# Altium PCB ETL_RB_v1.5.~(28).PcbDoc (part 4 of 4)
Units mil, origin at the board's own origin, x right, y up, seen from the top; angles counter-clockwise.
Board outline 5129.92 x 2224.41 mil, 8 copper layers (Top Layer, plane 1, M1, plane 2, plane 3, M2, plane 4, Bottom Layer), stack 36.907 mil thick; 212 components, 186 nets, 1961 pads, 978 vias.
Unrouted connection lines stored in the file: 395.
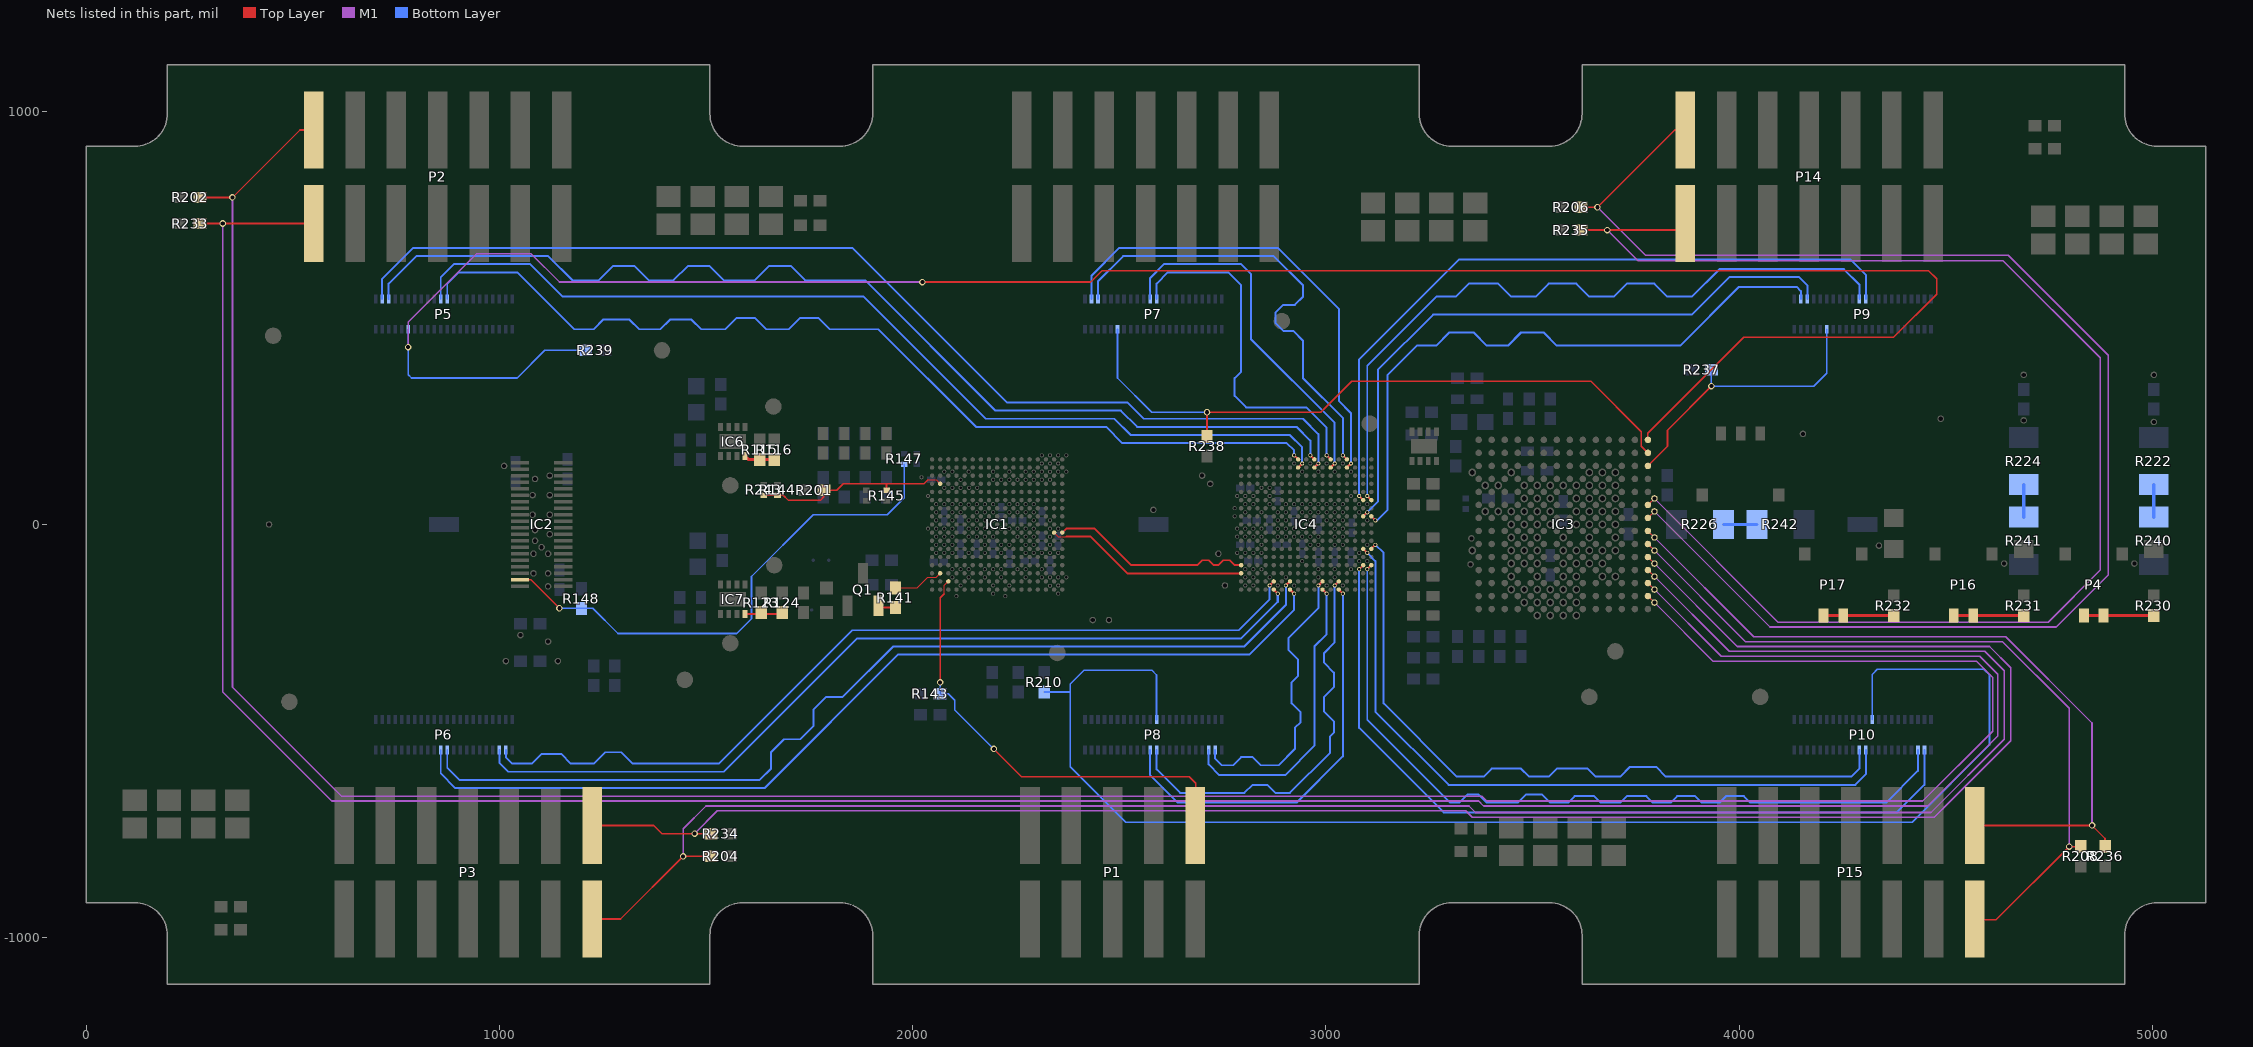
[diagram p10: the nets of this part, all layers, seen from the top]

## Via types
v1: diameter 15.75, hole 9.84, Top Layer to Bottom Layer, 978 vias

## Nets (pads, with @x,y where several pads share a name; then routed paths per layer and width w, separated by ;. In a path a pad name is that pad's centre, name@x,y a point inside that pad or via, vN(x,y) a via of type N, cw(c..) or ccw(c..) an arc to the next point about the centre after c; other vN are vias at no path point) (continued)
NetIC6_4: IC6.4 R115.1 R116.2 | length 74.1
  Top Layer w7.87: IC6.4@1594.49,165.35 1602.36,157.48 R115.1@1629.92,157.48 R116.2@1665.35,157.48
NetIC7_4: IC7.4 R123.1 R124.2 | length 92.2
  Top Layer w4.02: IC7.4@1594.49,-216.54 1681.1,-216.54 R124.2@1685.04,-212.6
NetP4_1: P4.1 P4.2 R230.2 | length 169.3
  Top Layer w8: P4.1@4834.65,-220.47 P4.2@4881.89,-220.47 R230.2@5003.94,-220.47
NetP8_11: P8.11 P10.12 R210.1 | length 3530.4
  Bottom Layer w4: R210.1@2318.9,-405.51 2381.89,-405.51 ; P8.11@2590.55,-472.44 2590.55,-364.17 2578.74,-352.36 2415.35,-352.36 2381.89,-385.83 2381.89,-405.51 ; P10.12@4322.83,-472.44 4322.83,-362.2 4334.65,-350.39 4592.52,-350.39 4606.3,-364.17 4606.3,-533.46 4419.29,-720.47 3011.81,-720.47 2515.75,-720.47 2381.89,-586.61 2381.89,-405.51
NetP16_1: P16.1 P16.2 R231.2 | length 169.3
  Top Layer w8: P16.1@4519.69,-220.47 P16.2@4566.93,-220.47 R231.2@4688.98,-220.47
NetP17_1: P17.1 P17.2 R232.2 | length 169.3
  Top Layer w8: P17.1@4204.72,-220.47 P17.2@4251.97,-220.47 R232.2@4374.02,-220.47
NetQ1_2: Q1.2 R141.2 | length 43
  Top Layer w5: Q1.2@1917.32,-196.85 1921.26,-200.79 R141.2@1958.66,-200.79
NetR222_2: R222.2 R240.1 | length 78.7
  Bottom Layer w8: R240.1@5003.94,17.72 R222.2@5003.94,96.46
NetR224_2: R224.2 R241.1 | length 78.7
  Bottom Layer w8: R241.1@4688.98,17.72 R224.2@4688.98,96.46
NetR226_2: R226.2 R242.1 | length 80.7
  Bottom Layer w8: R226.2@3962.6,0 R242.1@4043.31,0
ON0: IC3.A12 P2.1 pad.1@3795.28,-157.48 R233.1 | length 6976.4
  Top Layer w4: R233.1@275.59,728.35 v1(330.71,728.35) P2.1@551.18,728.35
  Top Layer w4.02: IC3.A12@3779.53,-141.73 pad.1@3795.28,-157.48
  M1 w4: v1(330.71,728.35) 330.71,-405.51 594.49,-669.29 3370.08,-669.29 3381.89,-681.1 4456.69,-681.1 4625.98,-511.81 4625.98,-362.2 4582.68,-318.9 3956.69,-318.9 pad.1@3795.28,-157.48
ON1: IC3.A10 P3.1 pad.1@3795.28,-94.49 R234.1 | length 4752.6
  Top Layer w4.02: P3.1@1224.41,-728.35 1374.02,-728.35 1393.7,-748.03 v1(1472.44,-748.03) R234.1@1511.81,-748.03 ; IC3.A10@3779.53,-78.74 pad.1@3795.28,-94.49
  M1 w4.02: v1(1472.44,-748.03) 1527.56,-692.91 3338.58,-692.91 3354.33,-708.66 4472.44,-708.66 4657.48,-523.62 4657.48,-346.46 4606.3,-295.28 3996.06,-295.28 pad.1@3795.28,-94.49
ON2: IC3.A6 P14.1 pad.1@3795.28,62.99 R235.1 | length 3370.3
  Top Layer w4: R235.1@3618.11,712.6 3854.33,712.6 P14.1@3870.08,728.35 ; IC3.A6@3779.53,47.24 pad.1@3795.28,62.99
  M1 w4: v1(3681.1,712.6) 3755.91,637.8 4639.76,637.8 4874.02,403.54 4874.02,-110.24 4748.03,-236.22 4094.49,-236.22 pad.1@3795.28,62.99
ON3: IC3.A8 P15.1 pad.1@3795.28,-31.5 R236.1 | length 1863
  Top Layer w4: IC3.A8@3779.53,-15.75 pad.1@3795.28,-31.5 ; P15.1@4570.87,-728.35 v1(4854.33,-728.35) 4885.83,-759.84 R236.1@4885.83,-779.53
  M1 w4: pad.1@3795.28,-31.5 4035.43,-271.65 4645.67,-271.65 4854.33,-480.32 v1(4854.33,-728.35)
PG0: IC3.A13 P2.2 pad.1@3795.28,-188.98 R202.1 | length 7018.5
  Top Layer w4.02: R202.1@275.59,791.34 v1(354.33,791.34) 517.72,954.72 P2.2@551.18,954.72 ; IC3.A13@3779.53,-173.23 pad.1@3795.28,-188.98
  M1 w4.02: v1(354.33,791.34) 354.33,-393.7 618.11,-657.48 3377.95,-657.48 3389.76,-669.29 4444.88,-669.29 4614.17,-500 4614.17,-370.08 4574.8,-330.71 3937.01,-330.71 pad.1@3795.28,-188.98
PG1: IC3.A11 P3.2 pad.1@3795.27,-125.98 R204.1 | length 4845.4
  Top Layer w4: P3.2@1224.41,-954.72 1293.31,-954.72 v1(1444.88,-803.15) R204.1@1511.81,-803.15 ; IC3.A11@3779.53,-110.24 pad.1@3795.27,-125.98
  M1 w4: v1(1444.88,-803.15) 1444.88,-736.22 1500,-681.1 3346.46,-681.1 3362.2,-696.85 4464.57,-696.85 4641.73,-519.68 4641.73,-354.33 4594.49,-307.09 3976.38,-307.09 pad.1@3795.27,-125.98
PG2: IC3.A7 P14.2 pad.1@3795.28,31.5 R206.1 | length 3534.2
  Top Layer w4.02: R206.1@3618.11,767.72 v1(3657.48,767.72) 3844.49,954.72 P14.2@3870.08,954.72 ; IC3.A7@3779.53,15.75 pad.1@3795.28,31.5
  M1 w4.02: v1(3657.48,767.72) 3773.62,651.57 4651.57,651.57 4893.7,409.45 4893.7,-122.05 4767.72,-248.03 4074.8,-248.03 pad.1@3795.28,31.5
PG3: IC3.A9 P15.2 pad.1@3795.28,-62.99 R208.1 | length 1849.1
  Top Layer w4.02: IC3.A9@3779.53,-47.24 pad.1@3795.28,-62.99 ; P15.2@4570.87,-954.72 4572.83,-956.69 4622.05,-956.69 v1(4799.21,-779.53) R208.1@4826.77,-779.53
  M1 w4.02: pad.1@3795.28,-62.99 4015.75,-283.46 4637.8,-283.46 4799.21,-444.88 v1(4799.21,-779.53)
READY0: IC1.R2 R141.1 | length 122.9
  Top Layer w3: R141.1@1958.66,-153.54 2011.81,-153.54 2037.4,-127.95 2057.09,-127.95 IC1.R2@2066.93,-118.11
REFCLKN: IC1.K17 IC4.P1 | length 493.4
  Top Layer w4.72: IC1.K17@2362.2,-19.68 2372.05,-9.84 2440.94,-9.84 2529.53,-98.42 2688.98,-98.42 2700.79,-86.61 2716.54,-86.61 2728.35,-98.42 2740.16,-98.42 2751.97,-86.61 2767.72,-86.61 2779.53,-98.42 IC4.P1@2795.28,-98.43
REFCLKP: IC1.K16 IC4.R1 | length 493.5
  Top Layer w3: IC1.K16@2342.52,-19.68 2352.36,-29.53 2372.05,-29.53
  Top Layer w4.72: 2372.05,-29.53 2431.1,-29.53 2519.68,-118.11 IC4.R1@2795.28,-118.11
RSSI: IC2.4 R147.2 R148.1 | length 1261
  Top Layer w4: IC2.4@1050,-133.86 1076.77,-133.86 v1(1145.67,-202.76)
  Bottom Layer w4: v1(1145.67,-202.76) R148.1@1198.82,-202.76 1226.38,-202.76 1287.4,-263.78 1574.8,-263.78 1610.24,-228.35 1610.24,-125.98 1759.84,23.62 1938.98,23.62 1980.31,64.96 R147.2@1980.31,145.67
RSTB0: IC3.A1 P5.16 R239.1 | length 5338.2
  Top Layer w4: v1(2023.62,586.61) 2431.1,586.61 2458.66,614.17 4458.66,614.17 4478.35,594.49 4478.35,557.09 4374.02,452.76 4011.81,452.76 3779.53,220.47 IC3.A1@3779.53,204.72
  M1 w4: v1(779.53,429.13) 779.53,490.16 944.88,655.51 1076.77,655.51 1145.67,586.61 v1(2023.62,586.61)
  Bottom Layer w4: P5.16@779.53,472.44 v1(779.53,429.13) 779.53,362.2 787.4,354.33 1043.31,354.33 1110.24,421.26 R239.1@1208.66,421.26
RSTB1: IC3.A2 P7.16 pad.1@2712.6,271.65 R238.1 | length 1618.4
  Top Layer w4: R238.1@2712.6,212.6 pad.1@2712.6,271.65 2988.19,271.65 3062.99,346.46 3641.73,346.46 3763.78,224.41 3763.78,188.98 IC3.A2@3779.53,173.23
  Bottom Layer w4: P7.16@2496.06,472.44 2496.06,354.33 2578.74,271.65 pad.1@2712.6,271.65
RSTB2: IC3.A3 P9.16 R237.1 | length 694.8
  Top Layer w4: IC3.A3@3779.53,141.73 3826.77,188.98 3826.77,228.35 v1(3933.07,334.65)
  Bottom Layer w4: R237.1@3933.07,374.02 v1(3933.07,334.65) 4181.1,334.65 4212.6,366.14 P9.16@4212.6,472.44
SC_I2C: IC1.T3 P1.1 R143.2 | length 1105.2
  Top Layer w3: 2076.77,-167.32 2076.77,-147.64 IC1.T3@2086.61,-137.79
  Top Layer w4: v1(2066.93,-381.89) 2066.93,-177.16 2076.77,-167.32 ; v1(2196.85,-543.31) 2263.78,-610.24 2383.86,-610.24 ; 2384.25,-610.63 2383.86,-610.24 ; P1.1@2685.04,-728.35 2685.04,-625.98 2669.29,-610.24 2383.86,-610.24
  Top Layer w39.37: P1.1@2684.25,-728.35 P1.1@2685.04,-728.35
  Bottom Layer w4: v1(2066.93,-381.89) R143.2@2066.93,-409.45 2086.61,-409.45 2102.36,-425.2 2102.36,-448.82 v1(2196.85,-543.31)
T_EDIN00N: IC4.U5 P6.22 pad.1@2883.86,-167.32 | length 2128.3
  Top Layer w5.12: IC4.U5@2874.02,-157.48 pad.1@2883.86,-167.32
  Bottom Layer w4.72: P6.22@1000,-545.28 1000,-576.77 1021.65,-598.43 1543.31,-598.43 1866.14,-275.59 2696.85,-275.59
  Bottom Layer w5.12: 2696.85,-275.59 2795.28,-275.59 2883.86,-187.01 pad.1@2883.86,-167.32
T_EDIN00P: IC4.T5 P6.21 pad.1@2864.17,-147.64 | length 2127.2
  Top Layer w5.12: pad.1@2864.17,-147.64 IC4.T5@2874.02,-137.8
  Bottom Layer w4.72: P6.21@1015.75,-545.28 1015.75,-562.99 1031.5,-578.74 1078.74,-578.74 1102.36,-555.12 1149.61,-555.12 1173.23,-578.74 1228.35,-578.74 1255.91,-551.18 1295.28,-551.18 1322.83,-578.74 1531.5,-578.74 1854.33,-255.91 2789.37,-255.91 2864.17,-181.1 pad.1@2864.17,-147.64
T_EDIN02N: IC4.U7 P6.31 pad.1@2923.23,-167.32 | length 2368.6
  Top Layer w5.12: IC4.U7@2913.39,-157.48 pad.1@2923.23,-167.32
  Bottom Layer w4.72: P6.31@858.27,-545.28 858.27,-602.36 893.7,-637.8 1641.73,-637.8 1964.57,-314.96 2814.96,-314.96 2923.23,-206.69 pad.1@2923.23,-167.32
T_EDIN02P: IC4.T7 P6.30 pad.1@2903.54,-147.64 | length 2367.7
  Top Layer w5.12: pad.1@2903.54,-147.64 IC4.T7@2913.39,-137.8
  Bottom Layer w4.72: P6.30@874.02,-545.28 874.02,-588.58 903.54,-618.11 1629.92,-618.11 1657.48,-590.55 1657.48,-551.18 1688.98,-519.68 1728.35,-519.68 1759.84,-488.19 1759.84,-448.82 1791.34,-417.32 1830.71,-417.32 1952.76,-295.28 2803.15,-295.28 2903.54,-194.88 pad.1@2903.54,-147.64
T_EDIN10N: IC4.U11 P8.22 pad.1@3001.97,-167.32 | length 725.6
  Top Layer w5.12: IC4.U11@2992.13,-157.48 pad.1@3001.97,-167.32
  Bottom Layer w4.72: P8.22@2716.54,-545.28 2716.54,-580.71 2742.13,-606.3 2901.57,-606.3 2972.44,-535.43 2972.44,-295.28 3001.97,-265.75 pad.1@3001.97,-167.32
T_EDIN10P: IC4.T11 P8.21 pad.1@2982.28,-147.64 | length 724.4
  Top Layer w5.12: pad.1@2982.28,-147.64 IC4.T11@2992.13,-137.8
  Bottom Layer w4.72: P8.21@2732.28,-545.28 2732.28,-566.93 2748.03,-582.68 2775.59,-582.68 2795.28,-562.99 2822.83,-562.99 2842.52,-582.68 2885.83,-582.68 2925.2,-543.31 2925.2,-492.13 2938.98,-478.35 2938.98,-454.72 2917.32,-433.07 2917.32,-381.89 2933.07,-366.14 2933.07,-326.77 2909.45,-303.15 2909.45,-275.59 2982.28,-202.76 pad.1@2982.28,-147.64
T_EDIN12N: IC4.U13 P8.31 pad.1@3041.34,-167.32 | length 1009.4
  Top Layer w5.12: IC4.U13@3031.5,-157.48 pad.1@3041.34,-167.32
  Bottom Layer w4.72: P8.31@2574.8,-545.28 2574.8,-606.3 2641.73,-673.23 2929.13,-673.23 3041.34,-561.02 pad.1@3041.34,-167.32
T_EDIN12P: IC4.T13 P8.30 pad.1@3021.65,-147.64 | length 1009.9
  Top Layer w5.12: pad.1@3021.65,-147.64 IC4.T13@3031.5,-137.8
  Bottom Layer w4.72: P8.30@2590.55,-545.28 2590.55,-592.52 2647.64,-649.61 2803.15,-649.61 2822.83,-629.92 2858.27,-629.92 2877.95,-649.61 2913.39,-649.61 3009.84,-553.15 3009.84,-513.78 3019.69,-503.94 3019.69,-476.38 2996.06,-452.76 2996.06,-417.32 3019.69,-393.7 3019.69,-358.27 2996.06,-334.65 2996.06,-311.02 3021.65,-285.43 pad.1@3021.65,-147.64
T_EDIN20N: IC4.P17 P10.22 pad.1@3100.39,-108.27 | length 1961.7
  Top Layer w5.12: pad.1@3100.39,-108.27 IC4.P17@3110.24,-98.43
  Bottom Layer w4.72: pad.1@3100.39,-108.27 3100.39,-472.44 3301.18,-673.23 3322.83,-673.23 3342.52,-653.54 3370.08,-653.54 3389.76,-673.23 3464.57,-673.23 3484.25,-653.54 3523.62,-653.54 3543.31,-673.23 3586.61,-673.23 3602.36,-657.48 3649.61,-657.48 3665.35,-673.23 3712.6,-673.23 3728.35,-657.48 3775.59,-657.48 3791.34,-673.23 3834.65,-673.23 3850.39,-657.48 3893.7,-657.48 3909.45,-673.23 3952.76,-673.23 3968.5,-657.48 4011.81,-657.48 4027.56,-673.23 4356.3,-673.23 4433.07,-596.46 P10.22@4433.07,-545.28
T_EDIN20P: IC4.P16 P10.21 pad.1@3080.71,-108.27 | length 1963.1
  Top Layer w5.12: pad.1@3080.71,-108.27 IC4.P16@3090.55,-98.43
  Bottom Layer w4.72: pad.1@3080.71,-108.27 3080.71,-492.13 3285.43,-696.85 4381.89,-696.85 4448.82,-629.92 P10.21@4448.82,-545.28
T_EDIN22N: IC4.M17 P10.31 pad.1@3120.08,-49.21 | length 1736.5
  Top Layer w5.12: IC4.M17@3110.24,-59.05 pad.1@3120.08,-49.21
  Bottom Layer w4.72: pad.1@3120.08,-49.21 3139.76,-68.9 3139.76,-433.07 3316.93,-610.24 3381.89,-610.24 3401.57,-590.55 3472.44,-590.55 3492.13,-610.24 3539.37,-610.24 3559.06,-590.55 3633.86,-590.55 3653.54,-610.24 3712.6,-610.24 3736.22,-586.61 3799.21,-586.61 3822.83,-610.24 4271.65,-610.24 4291.34,-590.55 P10.31@4291.34,-545.28
T_EDIN22P: IC4.M16 P10.30 pad.1@3100.39,-68.9 | length 1736
  Top Layer w5.12: IC4.M16@3090.55,-59.05 pad.1@3100.39,-68.9
  Bottom Layer w4.72: pad.1@3100.39,-68.9 3120.08,-88.58 3120.08,-452.76 3297.24,-629.92 4281.5,-629.92 4307.09,-604.33 P10.30@4307.09,-545.28
T_EDIN30N: IC4.H17 P9.21 pad.1@3120.08,9.84 | length 1540.9
  Top Layer w5.12: IC4.H17@3110.24,19.68 pad.1@3120.08,9.84
  Bottom Layer w4.72: pad.1@3124.02,9.84 3149.61,35.43 3149.61,362.2 3220.47,433.07 3267.72,433.07 3299.21,464.57 3358.27,464.57 3389.76,433.07 3440.94,433.07 3472.44,464.57 3527.56,464.57 3559.06,433.07 3858.27,433.07 4000,574.8 4139.76,574.8 4149.61,564.96 P9.21@4149.61,545.28
T_EDIN30P: IC4.H16 P9.22 pad.1@3100.39,29.53 | length 1542.9
  Top Layer w5.12: IC4.H16@3090.55,19.68 pad.1@3100.39,29.53
  Bottom Layer w4.72: pad.1@3100.39,29.53 3125.98,55.12 3125.98,374.02 3259.84,507.87 3885.83,507.87 3976.38,598.43 4145.67,598.43 4165.35,578.74 P9.22@4165.35,545.28
T_EDIN32N: IC4.F17 P9.30 pad.1@3100.39,68.9 | length 1746.1
  Top Layer w5.12: pad.1@3100.39,68.9 IC4.F17@3110.24,59.05
  Bottom Layer w4.72: pad.1@3100.39,68.9 3100.39,383.86 3267.72,551.18 3314.96,551.18 3346.46,582.68 3417.32,582.68 3448.82,551.18 3507.87,551.18 3539.37,582.68 3606.3,582.68 3637.8,551.18 3696.85,551.18 3728.35,582.68 3795.28,582.68 3826.77,551.18 3885.83,551.18 3952.76,618.11 4253.94,618.11 4291.34,580.71 P9.30@4291.34,545.28
T_EDIN32P: IC4.F16 P9.31 pad.1@3080.71,68.9 | length 1745.8
  Top Layer w5.12: pad.1@3080.71,68.9 IC4.F16@3090.55,59.05
  Bottom Layer w4.72: pad.1@3080.71,68.9 3080.71,399.61 3322.83,641.73 4269.69,641.73 4307.09,604.33 P9.31@4307.09,545.28
T_EDIN40N: IC4.A14 P7.22 pad.1@3041.34,167.32 | length 1144.7
  Top Layer w5.12: pad.1@3041.34,167.32 IC4.A14@3051.18,157.48
  Bottom Layer w4.72: P7.22@2448.82,545.28 2448.82,588.58 2509.84,649.61 2874.02,649.61 2944.88,578.74 2944.88,551.18 2925.2,531.5 2897.64,531.5 2877.95,511.81 2877.95,488.19 2897.64,468.5 2921.26,468.5 2944.88,444.88 2944.88,354.33 3041.34,257.87 pad.1@3041.34,167.32
T_EDIN40P: IC4.B14 P7.21 pad.1@3061.02,147.64 | length 1144.6
  Top Layer w5.12: IC4.B14@3051.18,137.8 pad.1@3061.02,147.64
  Bottom Layer w4.72: P7.21@2433.07,545.28 2433.07,602.36 2500,669.29 2883.86,669.29 3031.5,521.65 3031.5,299.21 3061.02,269.69 pad.1@3061.02,147.64
T_EDIN42N: IC4.A12 P7.31 pad.1@3001.97,167.32 | length 875.9
  Top Layer w5.12: pad.1@3001.97,167.32 IC4.A12@3011.81,157.48
  Bottom Layer w4.72: P7.31@2590.55,545.28 2590.55,582.68 2618.11,610.24 2763.78,610.24 2795.28,578.74 2795.28,370.08 2779.53,354.33 2779.53,311.02 2807.09,283.46 2952.76,283.46 3001.97,234.25 pad.1@3001.97,167.32
T_EDIN42P: IC4.B12 P7.30 pad.1@3021.65,147.64 | length 875.5
  Top Layer w5.12: IC4.B12@3011.81,137.8 pad.1@3021.65,147.64
  Bottom Layer w4.72: P7.30@2574.8,545.28 2574.8,596.46 2608.27,629.92 2795.28,629.92 2818.9,606.3 2818.9,448.82 3021.65,246.06 pad.1@3021.65,147.64
T_EDIN50N: IC4.A10 P5.22 pad.1@2962.6,167.32 | length 2617.9
  Top Layer w5.12: pad.1@2962.6,167.32 IC4.A10@2972.44,157.48
  Bottom Layer w4.72: P5.22@732.28,545.28 732.28,582.68 799.21,649.61 1118.11,649.61 1177.17,590.55 1240.16,590.55 1275.59,625.98 1326.77,625.98 1362.2,590.55 1421.26,590.55 1456.69,625.98 1507.87,625.98 1543.31,590.55 1618.11,590.55 1653.54,625.98 1704.72,625.98 1740.16,590.55 1885.83,590.55 2200.79,275.59 2503.94,275.59 2543.31,236.22 2929.13,236.22 2962.6,202.76 pad.1@2962.6,167.32
T_EDIN50P: IC4.B10 P5.21 pad.1@2982.28,147.64 | length 2617.5
  Top Layer w5.12: IC4.B10@2972.44,137.8 pad.1@2982.28,147.64
  Bottom Layer w4.72: P5.21@716.54,545.28 716.54,594.49 791.34,669.29 1854.33,669.29 2228.35,295.28 2519.69,295.28 2559.06,255.91 2944.88,255.91 2982.28,218.5 pad.1@2982.28,147.64
T_EDIN52N: IC4.A8 P5.31 pad.1@2923.23,167.32 | length 2387.1
  Top Layer w5.12: pad.1@2923.23,167.32 IC4.A8@2933.07,157.48
  Bottom Layer w4.72: P5.31@874.02,545.28 874.02,582.68 901.57,610.24 1043.31,610.24 1181.1,472.44 1228.35,472.44 1251.97,496.06 1314.96,496.06 1338.58,472.44 1389.76,472.44 1413.39,496.06 1464.57,496.06 1488.19,472.44 1547.24,472.44 1574.8,500 1618.11,500 1645.67,472.44 1700.79,472.44 1728.35,500 1771.65,500 1799.21,472.44 1917.32,472.44 2153.54,236.22 2468.5,236.22 2507.87,196.85 2905.51,196.85 2923.23,179.13 pad.1@2923.23,167.32
T_EDIN52P: IC4.B8 P5.30 pad.1@2942.91,147.64 | length 2387.6
  Top Layer w5.12: IC4.B8@2933.07,137.8 pad.1@2942.91,147.64
  Bottom Layer w4.72: P5.30@858.27,545.28 858.27,598.43 889.76,629.92 1074.8,629.92 1153.54,551.18 1881.89,551.18 2177.17,255.91 2488.19,255.91 2527.56,216.54 2913.39,216.54 2942.91,187.01 pad.1@2942.91,147.64
Vref: IC1.D2 R144.2 R145.2 R201.2 R243.2 | length 481.5
  Top Layer w3: 2037.4,108.27 2057.09,108.27 IC1.D2@2066.93,98.43
  Top Layer w4: R243.2@1639.76,70.87 R144.2@1673.23,70.87 1687.01,70.87 1698.82,59.06 1777.56,59.06 1785.43,66.93 R201.2@1785.43,82.68 1816.93,82.68 1832.68,98.43 1937.01,98.43 2027.56,98.43 2037.4,108.27
  Top Layer w4.02: R145.2@1937.01,82.68 1937.01,98.43
pads on no net: IC1.A3 IC1.A4 IC1.A5 IC1.A6 IC1.A7 IC1.A9 IC1.A11 IC1.A13 IC1.B3 IC1.B4 IC1.B5 IC1.B6 IC1.B7 IC1.B9 IC1.B11 IC1.B13 IC1.C2 IC1.C6 IC1.C7 IC1.C8 IC1.C10 IC1.C12 IC1.C16 IC1.C17 IC1.D6 IC1.D7 IC1.D8 IC1.D10 IC1.D12 IC1.D14 IC1.D15 IC1.D16 IC1.D17 IC1.E2 IC1.E7 IC1.E10 IC1.E11 IC1.E12 IC1.E13 IC1.E14 IC1.E15 IC1.E16 IC1.E17 IC1.F7 IC1.F10 IC1.F11 IC1.F12 IC1.F13 IC1.F14 IC1.F15 IC1.G14 IC1.G15 IC1.G16 IC1.G17 IC1.H4 IC1.H14 IC1.H15 IC1.J4 IC1.J14 IC1.J15 IC1.J16 IC1.J17 IC1.K4 IC1.K14 IC1.K15 IC1.L4 IC1.L5 IC1.L7 IC1.L8 IC1.L9 IC1.L14 IC1.L15 IC1.L16 IC1.L17 IC1.M4 IC1.M5 IC1.M6 IC1.M7 IC1.M9 IC1.M10 IC1.M11 IC1.M14 IC1.M15 IC1.N4 IC1.N5 IC1.N6 IC1.N7 IC1.N8 IC1.N9 IC1.N10 IC1.N11 IC1.N12 IC1.N14 IC1.N15 IC1.N16 IC1.N17 IC1.P1 IC1.P6 IC1.P8 IC1.P10 IC1.P11 IC1.P12 IC1.P15 IC1.R1 IC1.R3 IC1.R6 IC1.R8 IC1.R10 IC1.R11 IC1.R12 IC1.R15 IC1.T1 IC1.T2 IC1.T6 IC1.T8 IC1.T12 IC1.T14 IC1.T15 IC1.U1 IC1.U6 IC1.U8 IC1.U12 IC1.U14 IC1.U15 IC2.2 IC2.20 IC2.22 IC2.25 IC2.26 IC2.27 IC2.28 IC2.31 IC2.33 IC3.A4 IC3.A5 IC3.A14 IC3.B1 IC3.B2 IC3.B3 IC3.B4 IC3.B5 IC3.B6 IC3.B7 IC3.B8 IC3.B9 IC3.B10 IC3.B11 IC3.B12 IC3.B13 IC3.B14 IC3.C1 IC3.C2 IC3.C3 IC3.C4 IC3.C5 IC3.C6 IC3.C7 IC3.C8 IC3.C9 IC3.C10 IC3.C11 IC3.C12 IC3.C13 IC3.C14 IC3.D1 IC3.D2 IC3.D3 IC3.D12 IC3.D13 IC3.D14 IC3.E1 IC3.E2 IC3.E3 IC3.E12 IC3.E13 IC3.E14 IC3.F1 IC3.F2 IC3.F3 IC3.F12 IC3.F13 IC3.F14 IC3.G1 IC3.G2 IC3.G3 IC3.G4 IC3.H1 IC3.H2 IC3.H3 IC3.H4 IC3.J1 IC3.J2 IC3.J3 IC3.J4 IC3.K1 IC3.K2 IC3.K3 IC3.L1 IC3.L2 IC3.L3 IC3.M1 IC3.M2 IC3.M3 IC3.M7 IC3.M8 IC3.M9 IC3.M10 IC3.M11 IC3.M12 IC3.N1 IC3.N2 IC3.N3 IC3.N5 IC3.N7 IC3.N8 IC3.N9 IC3.N10 IC3.N11 IC3.N12 IC3.N13 IC3.N14 IC3.P1 IC3.P2 IC3.P3 IC3.P5 IC4.A1 IC4.A2 IC4.A3 IC4.A4 IC4.A5 IC4.A6 IC4.A7 IC4.A9 IC4.A11 IC4.A13 IC4.A15 IC4.A16 IC4.A17 IC4.B1 IC4.B2 IC4.B3 IC4.B4 IC4.B5 IC4.B6 IC4.B7 IC4.B9 IC4.B11 IC4.B13 IC4.B15 IC4.B16 IC4.B17 IC4.C1 IC4.C2 IC4.C3 IC4.C4 IC4.C5 IC4.C6 IC4.C7 IC4.C8 IC4.C9 IC4.C10 IC4.C11 IC4.C12 IC4.C13 IC4.C14 IC4.C15 IC4.C16 IC4.C17 IC4.D1 IC4.D2 IC4.D4 IC4.D5 IC4.D6 IC4.D7 IC4.D8 IC4.D9 IC4.D10 IC4.D11 IC4.D12 IC4.D13 IC4.D14 IC4.D15 IC4.D16 IC4.D17 IC4.E1 IC4.E2 IC4.E5 IC4.E6 IC4.E7 IC4.E10 IC4.E11 IC4.E12 IC4.E13 IC4.E14 IC4.E15 IC4.E16 IC4.E17 IC4.F5 IC4.F6 IC4.F7 IC4.F10 IC4.F11 IC4.F12 IC4.F13 IC4.F14 IC4.F15 IC4.G14 IC4.G15 IC4.G16 IC4.G17 IC4.H4 IC4.H14 IC4.H15 IC4.J4 IC4.J14 IC4.J15 IC4.J16 IC4.J17 IC4.K4 IC4.K14 IC4.K15 IC4.K16 IC4.K17 IC4.L1 IC4.L4 IC4.L5 IC4.L6 IC4.L7 IC4.L8 IC4.L9 IC4.L14 IC4.L15 IC4.L16 IC4.L17 IC4.M1 IC4.M4 IC4.M5 IC4.M6 IC4.M7 IC4.M8 IC4.M9 IC4.M10 IC4.M11 IC4.M14 IC4.M15 IC4.N4 IC4.N5 IC4.N6 IC4.N7 IC4.N8 IC4.N9 IC4.N10 IC4.N11 IC4.N12 IC4.N13 IC4.N14 IC4.N15 IC4.N16 IC4.N17 IC4.P4 IC4.P5 IC4.P6 IC4.P7 IC4.P8 IC4.P9 IC4.P10 IC4.P11 IC4.P12 IC4.P13 IC4.P14 IC4.P15 IC4.R2 IC4.R3 IC4.R4 IC4.R5 IC4.R6 IC4.R7 IC4.R8 IC4.R9 IC4.R10 IC4.R11 IC4.R12 IC4.R13 IC4.R14 IC4.R15 IC4.R16 IC4.R17 IC4.T1 IC4.T2 IC4.T4 IC4.T6 IC4.T8 IC4.T9 IC4.T10 IC4.T12 IC4.T14 IC4.T15 IC4.T16 IC4.T17 IC4.U1 IC4.U4 IC4.U6 IC4.U8 IC4.U9 IC4.U10 IC4.U12 IC4.U14 IC4.U15 IC4.U16 IC4.U17 IC5.2 IC5.3 IC6.2 IC6.5 IC6.7 IC7.2 IC7.5 IC7.7 JMP1.9 JMP2.9 P1.3 P1.5 P1.7 P2.3 P2.4 P3.3 P3.4 P4.4 P6.16 P8.16 P10.16 P11.1 P11.2 P12.5 P14.3 P14.4 P15.3 P15.4 P16.4 P17.4
copper on no net: | length 2007.9
  Top Layer w6: 4990.16,-787.4 4990.16,-856.3 5088.58,-856.3 5088.58,-787.4 ; 4990.16,-787.4 4990.16,-718.5 ; 4990.16,-787.4 5088.58,-787.4 ; 4990.16,-718.5 4990.16,-639.76 ; 4990.16,-718.5 5088.58,-718.5 ; 4990.16,-639.76 4990.16,-570.87 ; 4990.16,-639.76 5088.58,-639.76 ; 4990.16,-570.87 4990.16,-501.97 ; 4990.16,-570.87 5088.58,-570.87 ; 4990.16,-501.97 4990.16,-433.07 ; 4990.16,-501.97 5088.58,-501.97 ; 4990.16,-433.07 4990.16,-364.17 ; 4990.16,-433.07 5088.58,-433.07 ; 4990.16,-364.17 4990.16,-295.28 5088.58,-295.28 5088.58,-364.17 ; 4990.16,-364.17 5088.58,-364.17 ; 5088.58,-787.4 5088.58,-718.5 ; 5088.58,-718.5 5088.58,-639.76 ; 5088.58,-639.76 5088.58,-570.87 ; 5088.58,-570.87 5088.58,-501.97 ; 5088.58,-501.97 5088.58,-433.07 ; 5088.58,-433.07 5088.58,-364.17

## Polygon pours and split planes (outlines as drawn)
GND on plane 1 (split plane): 271 vertices, not listed, extent 20.1,-1092.11 5109.82,1092.11
1V2_RB on plane 2 (split plane): 271 vertices, not listed, extent 20.1,-1092.11 5109.82,1092.11
GND on plane 2 (split plane): 3224.74,-129.59 3226.4,-130.69 3228.35,-131.08 3354.33,-131.08 3356.28,-130.69 3357.94,-129.59 3372.19,-115.33 3621.9,-115.33 4012.14,-505.57 4013.8,-506.68 4015.75,-507.07 4220.33,-507.07 4315.77,-602.51 4315.77,-870.89 3988.33,-870.89 3741.79,-624.35 3740.14,-623.24 3738.19,-622.85 3737.36,-623.02 3736.53,-622.85 3088.73,-622.85 2972.11,-506.24 2970.45,-505.13 2968.5,-504.74 2620.08,-504.74 2618.13,-505.13 2616.47,-506.24 2579.07,-543.64 2577.97,-545.29 2577.58,-547.24 2577.58,-600.25 2553.01,-624.82 681.25,-624.82 664.55,-608.12 664.55,-376.13 681.25,-359.43 1653.54,-359.43 1655.49,-359.04 1657.15,-357.94 1882.03,-133.05 2017.72,-133.05 2019.67,-132.66 2021.32,-131.56 2059.2,-93.68 2903.54,-93.68 2905.49,-93.29 2907.15,-92.19 2925.34,-74 3041.34,-74 3043.29,-73.61 3044.94,-72.5 3092.66,-24.78 3119.94,-24.78
GND on plane 2 (split plane): 4485.06,623.87 4485.06,366.28 4440.8,322.03 4037.54,322.03 3895.34,464.23 3893.68,465.34 3891.73,465.73 3230.31,465.73 3228.36,465.34 3226.71,464.23 3017.57,255.1 2523.62,255.1 2521.67,254.71 2520.02,253.6 2360.09,93.68 2187.15,93.68 2168.96,111.87 2167.31,112.98 2165.35,113.37 2137.94,113.37 1783.13,468.17 1781.48,469.28 1779.53,469.66 1232.28,469.66 1230.33,469.28 1228.68,468.17 1082.53,322.03 743.29,322.03 743.29,446.71 873.68,577.1 874.79,578.76 875.18,580.71 875.18,616 935.18,676 4432.93,676
1V2B on plane 3 (split plane): 782.3,-450.64 685.37,-547.58 684.27,-549.23 683.88,-551.18 683.88,-649.61 684.27,-651.56 685.37,-653.21 687.03,-654.32 688.98,-654.7 2708.66,-654.7 2710.61,-654.32 2712.27,-653.21 2713.37,-651.56 2713.76,-649.61 2713.76,-476.38 2713.37,-474.43 2712.27,-472.77 2710.61,-471.67 2708.66,-471.28 2446.99,-471.28 2386.99,-411.27 2386.99,-339.74 2947.66,-339.74 2947.66,-1092.11 1923.64,-1092.11 1923.64,-994.09 1923.64,-994.05 1923.26,-985.48 1922.14,-976.93 1920.27,-968.51 1917.68,-960.29 1914.38,-952.33 1910.4,-944.68 1905.76,-937.41 1900.51,-930.57 1894.69,-924.21 1888.33,-918.38 1881.49,-913.13 1874.22,-908.5 1866.57,-904.52 1858.61,-901.22 1850.38,-898.63 1841.97,-896.76 1833.42,-895.64 1824.85,-895.26 1824.8,-895.26 1588.58,-895.26 1588.53,-895.26 1579.97,-895.64 1571.42,-896.76 1563,-898.63 1554.78,-901.22 1546.81,-904.52 1539.17,-908.5 1531.89,-913.13 1525.05,-918.38 1518.7,-924.21 1512.87,-930.57 1507.62,-937.41 1502.99,-944.68 1499.01,-952.33 1495.71,-960.29 1493.12,-968.51 1491.25,-976.93 1490.12,-985.48 1489.75,-994.05 1489.75,-994.09 1489.75,-1092.11 216.95,-1092.11 216.95,-994.09 216.94,-994.05 216.57,-985.48 215.44,-976.93 213.58,-968.51 210.98,-960.29 207.68,-952.33 203.7,-944.68 199.07,-937.41 193.82,-930.57 188,-924.21 181.64,-918.38 174.8,-913.13 167.53,-908.5 159.88,-904.52 151.91,-901.22 143.69,-898.63 135.27,-896.76 126.72,-895.64 118.16,-895.26 118.11,-895.26 20.1,-895.26 20.1,-320.06 782.3,-320.06
GND on plane 3 (split plane): 2782.3,557.23 2722.3,497.22 2610.24,497.22 2608.29,496.84 2606.63,495.73 2579.07,468.17 2577.97,466.52 2577.58,464.57 2577.58,342.52 2577.97,340.57 2579.07,338.91 2580.73,337.81 2582.68,337.42 2917.32,337.42 2919.27,337.81 2920.93,338.91 3210.77,628.76 4483.09,628.76 4483.09,517.86 4427.02,461.79 4003.94,461.79 4001.99,461.4 4000.33,460.3 3999.23,458.64 3998.84,456.69 3998.84,-452.76 3999.23,-454.71 4000.33,-456.36 4001.99,-457.47 4003.94,-457.85 4424.04,-457.85 4424.04,-691.75 3744.09,-691.75 3742.14,-692.14 3740.49,-693.25 3739.38,-694.9 3739,-696.85 3739,-1092.11 3640.18,-1092.11 3640.18,-994.09 3640.17,-994.05 3639.8,-985.48 3638.67,-976.93 3636.81,-968.51 3634.21,-960.29 3630.91,-952.33 3626.93,-944.68 3622.3,-937.41 3617.05,-930.56 3611.22,-924.21 3604.87,-918.38 3598.03,-913.13 3590.76,-908.5 3583.11,-904.52 3575.14,-901.22 3566.92,-898.63 3558.5,-896.76 3549.95,-895.64 3541.39,-895.26 3541.34,-895.26 3305.12,-895.26 3305.07,-895.26 3296.5,-895.64 3287.96,-896.76 3279.54,-898.63 3271.31,-901.22 3263.35,-904.52 3255.7,-908.5 3248.43,-913.13 3241.59,-918.38 3235.23,-924.21 3229.41,-930.57 3224.16,-937.41 3219.53,-944.68 3215.54,-952.33 3212.24,-960.29 3209.65,-968.51 3207.79,-976.93 3206.66,-985.48 3206.29,-994.05 3206.28,-994.09 3206.28,-1092.11 2957.85,-1092.11 2957.85,-334.65 2957.47,-332.69 2956.36,-331.04 2954.71,-329.94 2952.76,-329.55 2381.89,-329.55 2379.94,-329.94 2378.28,-331.04 2377.18,-332.69 2376.79,-334.65 2376.79,-413.39 2377.18,-415.34 2378.28,-416.99 2441.28,-479.98 2442.93,-481.09 2444.88,-481.48 2703.56,-481.48 2703.56,-644.51 694.07,-644.51 694.07,-553.29 789.51,-457.85 984.25,-457.85 986.2,-457.47 987.86,-456.36 988.96,-454.71 989.35,-452.76 989.35,231.12 1141.73,231.12 1143.68,231.51 1145.34,232.62 1146.44,234.27 1146.83,236.22 1146.83,472.44 1146.44,474.39 1145.34,476.05 1143.68,477.15 1141.73,477.54 733.44,477.54 733.44,664.19 1354.33,664.19 1356.28,664.58 1357.94,665.69 1359.04,667.34 1359.43,669.29 1359.43,801.99 2299.21,801.99 2301.16,802.38 2302.82,803.48 2401.24,901.91 2402.35,903.56 2402.74,905.51 2402.74,1038.21 2782.3,1038.21
1V2A on plane 3 (split plane): 1349.23,807.09 1349.23,674.39 728.35,674.39 726.4,674 724.74,672.9 723.64,671.24 723.25,669.29 723.25,472.44 723.64,470.49 724.74,468.84 726.4,467.73 728.35,467.34 1136.63,467.34 1136.63,241.32 984.25,241.32 982.3,240.93 980.65,239.83 979.54,238.17 979.15,236.22 979.15,-447.66 792.5,-447.66 792.5,-314.96 792.11,-313.01 791.01,-311.36 789.35,-310.25 787.4,-309.86 20.1,-309.86 20.1,183.88 118.11,183.88 120.06,184.27 121.71,185.37 122.82,187.03 123.21,188.98 123.21,809.86 259.84,809.86 261.79,810.25 263.45,811.36 494.24,1042.15 1349.23,1042.15
LV_RB on plane 3 (split plane): 183 vertices, not listed, extent 20.1,194.07 5109.82,1092.11
1V5A on plane 3 (split plane): 3754.74,-329.55 3372.19,-329.55 3150.77,-108.12 3150.77,269.54 3269.83,388.6 3754.74,388.6
1V2D on plane 3 (split plane): 4372.85,275.59 4373.24,273.64 4374.35,271.99 4376,270.88 4377.95,270.49 5109.82,270.49 5109.82,-895.26 5011.81,-895.26 5011.76,-895.26 5003.2,-895.64 4994.65,-896.76 4986.23,-898.63 4978.01,-901.22 4970.04,-904.52 4962.39,-908.5 4955.12,-913.13 4948.28,-918.38 4941.92,-924.21 4936.1,-930.57 4930.85,-937.41 4926.22,-944.68 4922.24,-952.33 4918.94,-960.29 4916.34,-968.51 4914.48,-976.93 4913.35,-985.48 4912.98,-994.05 4912.97,-994.09 4912.97,-1092.11 3749.19,-1092.11 3749.19,-701.95 4429.13,-701.95 4431.08,-701.56 4432.74,-700.46 4433.84,-698.8 4434.23,-696.85 4434.23,-452.76 4433.84,-450.81 4432.74,-449.15 4431.08,-448.05 4429.13,-447.66 4009.03,-447.66 4009.03,451.59 4372.85,451.59
1V5D on plane 3 (split plane): 3616.95,-168.13 3532.66,-168.13 3532.66,110.24 3532.27,112.19 3531.16,113.84 3529.51,114.95 3527.56,115.33 3301.32,115.33 3253.13,163.53 3253.13,215.37 3616.95,215.37
1V2C on plane 3 (split plane): 4679.94,748.03 4680.33,746.08 4681.43,744.43 4683.09,743.32 4685.04,742.93 5026.4,742.93 5026.4,280.69 4383.05,280.69 4383.05,451.59 4429.13,451.59 4431.08,451.98 4432.74,453.09 4491.79,512.14 4492.9,513.8 4493.29,515.75 4493.29,633.86 4492.9,635.81 4491.79,637.46 4490.14,638.57 4488.19,638.96 3208.66,638.96 3206.71,638.57 3205.06,637.46 2915.21,347.62 2587.78,347.62 2587.78,462.46 2612.35,487.03 2724.41,487.03 2726.36,487.42 2728.01,488.52 2791.01,551.51 2792.11,553.17 2792.5,555.12 2792.5,1038.21 3046.08,1038.21 3046.08,818.9 3046.47,816.95 3047.58,815.29 3049.23,814.19 3051.18,813.8 3732.28,813.8 3734.23,814.19 3735.89,815.29 3958.8,1038.21 4679.94,1038.21
GND on plane 4 (split plane): 271 vertices, not listed, extent 20.1,-1092.11 5109.82,1092.11

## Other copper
Top Layer:
  rectangle net GND: 1505.91,181.1 1525.59,226.38
  rectangle net GND: 1505.91,183.07 1537.4,218.5
  rectangle net GND: 4704.72,720.47 5015.75,826.77
  rectangle net 1V2C: 4704.72,598.43 5015.75,704.72
  rectangle net LV_RB: 2342.52,814.96 2385.83,870.08
  rectangle net LV_RB: 2307.09,917.32 2346.46,1047.24
  rectangle net GND: 3082.68,751.97 3389.76,846.46
  rectangle net 1V2_RB: 2968.5,637.8 3389.76,736.22
  rectangle net GND: 1370.08,767.72 1685.04,850.39
  rectangle net 1V2A: 1244.09,633.86 1688.98,751.97
  rectangle net GND: 90.55,-830.71 397.64,-708.66
  rectangle net 1V2B: 90.55,-692.91 393.7,-574.8
  rectangle net GND: 842.52,-818.9 1086.61,-633.86
  rectangle net GND: 901.57,-1051.18 1086.61,-814.96
  rectangle net 1V2B: 511.81,-1047.24 826.77,-862.2
  rectangle net 1V2B: 511.81,-874.02 748.03,-633.86
  rectangle net GND: 3421.26,-858.27 3822.83,-779.53
  rectangle net 1V2D: 3421.26,-755.91 3881.89,-637.8
  region net 1V2_RB: 2976.38,874.02 2740.16,874.02 2740.16,633.86 2976.38,633.86
  region net 1V2_RB: 2976.38,1047.24 2677.17,1047.24 2677.17,862.2 2976.38,862.2
  region net GND: 2586.61,1047.24 2401.57,1047.24 2401.57,811.02 2586.61,811.02
  region net GND: 2657.48,822.83 2401.57,822.83 2401.57,633.86 2657.48,633.86
  region net 1V2A: 1263.78,877.95 1027.56,877.95 1027.56,633.86 1263.78,633.86
  region net 1V2A: 1263.78,1047.24 964.57,1047.24 964.57,862.2 1263.78,862.2
  region net GND: 877.95,1051.18 688.98,1051.18 688.98,814.96 877.95,814.96
  region net GND: 944.88,822.83 688.98,822.83 688.98,633.86 944.88,633.86
  region net 1V2C: 4570.87,874.02 4346.46,874.02 4346.46,633.86 4570.87,633.86
  region net 1V2C: 4570.87,1047.24 4279.53,1047.24 4279.53,862.2 4570.87,862.2
  region net GND: 4192.91,1047.24 4007.87,1047.24 4007.87,811.02 4192.91,811.02
  region net GND: 4263.78,822.83 4007.87,822.83 4007.87,633.86 4263.78,633.86
  rectangle net 1V2D: 3858.27,-874.02 4094.49,-633.86
  rectangle net 1V2D: 3858.27,-1047.24 4173.23,-862.2
  rectangle net GND: 4248.03,-1047.24 4433.07,-811.02
  rectangle net GND: 4188.98,-822.83 4433.07,-637.8
  rectangle net GND: 3842.52,55.12 3925.2,129.92
  rectangle net BV2: 4283.46,-110.24 4397.64,-35.43
  rectangle: 4460.63,-110.24 4503.94,-35.43
  rectangle: 4775.59,-114.17 4822.83,-35.43
  rectangle net BV1: 4598.43,-114.17 4712.6,-35.43
  rectangle net BV0: 4913.39,-114.17 5027.56,-35.43
  rectangle: 4082.68,-110.24 4173.23,-35.43
  rectangle: 4082.68,55.12 4165.35,129.92
  rectangle net GND: 1494.09,-200.79 1521.65,-153.54
  rectangle net GND: 1519.69,-200.79 1537.4,-163.39
  rectangle net GND: 3157.48,171.26 3212.6,206.69
  text "1" at 5068.74,-831.54 h60 r90
  text "'.Pcb_File_Name_No_Path'     '.Layer_Name'    '.Print_Date'    '.Print_Time'" at 391.89,-1233.79 h60
M1:
  text "3" at 5068.74,-698.66 h60 r90
  text "'.Pcb_File_Name_No_Path'    '.Layer_Name'    '.Print_Date'    '.Print_Time'" at 391.89,-1235.91 h60
M2:
  text "6" at 5068.74,-487.05 h60 r90
  text "'.Pcb_File_Name_No_Path'    '.Layer_Name'    '.Print_Date'    '.Print_Time'" at 391.89,-1235.91 h60
Bottom Layer:
  rectangle net GND: 1498.03,181.1 1525.59,226.38
  rectangle net GND: 1476.38,-200.79 1523.62,-153.54
  rectangle net GND: 2311.02,489.17 2759.84,528.54
  rectangle net GND: 1027.56,82.68 1098.43,122.05
  rectangle net GND: 1110.24,94.49 1177.17,129.92
  rectangle net GND: 1106.3,-129.92 1157.48,-94.49
  rectangle net GND: 582.68,366.14 704.72,500
  rectangle net GND: 2311.02,366.14 2417.32,496.06
  rectangle net GND: 2507.87,366.14 2578.74,496.06
  rectangle net GND: 4224.41,366.14 4295.28,496.06
  rectangle net GND: 4003.94,366.14 4137.8,528.54
  rectangle net GND: 4003.94,489.17 4476.38,528.54
  rectangle net GND: 791.34,366.14 862.2,496.06
  rectangle net GND: 870.08,-496.06 940.94,-448.82
  rectangle net GND: 870.08,-452.76 972.44,-366.14
  rectangle net GND: 4334.65,-496.06 4374.02,-448.82
  rectangle net GND: 4334.65,-452.76 4405.51,-366.14
  rectangle net GND: 4460.63,-500 4594.49,-366.14
  rectangle net GND: 2653.54,-452.76 2688.98,-366.14
  rectangle net GND: 2602.36,-496.06 2657.48,-366.14
  rectangle net GND: 2744.09,-500 2877.95,-366.14
  rectangle net GND: 1027.56,-500 1161.42,-366.14
  region net GND: 1161.42,-489.17 688.98,-489.17 688.98,-528.54 1161.42,-528.54
  region net GND: 2877.95,-489.17 2405.51,-489.17 2405.51,-528.54 2877.95,-528.54
  region net GND: 4594.49,-489.17 4122.05,-489.17 4122.05,-528.54 4594.49,-528.54
  rectangle net GND: 582.68,488.19 1035.43,527.56
  rectangle net 1V2_RB: 996.06,133.86 1035.43,165.35
  rectangle net 2V5TX: 1175.2,141.73 1206.69,173.23
  rectangle net 2V5RX: 1106.3,-173.23 1137.8,-141.73
  rectangle net 1V2C: 2665.35,365.16 2736.22,483.27
  rectangle net 1V2C: 2586.61,365.16 2657.48,483.27
  rectangle net 1V2D: 4303.15,365.16 4374.02,483.27
  rectangle net 1V2C: 4381.89,365.16 4452.76,483.27
  region net 1V2D: 4295.28,-365.16 4224.41,-365.16 4224.41,-483.27 4295.28,-483.27
  region net 1V2D: 4216.54,-365.16 4145.67,-365.16 4145.67,-483.27 4216.54,-483.27
  region net 1V2B: 2578.74,-365.16 2507.87,-365.16 2507.87,-483.27 2578.74,-483.27
  region net 1V2B: 2500,-365.16 2429.13,-365.16 2429.13,-483.27 2500,-483.27
  region net 1V2B: 783.46,-365.16 712.6,-365.16 712.6,-483.27 783.46,-483.27
  region net 1V2A: 862.2,-365.16 791.34,-365.16 791.34,-483.27 862.2,-483.27
  rectangle net 1V2A: 870.08,365.16 940.94,483.27
  rectangle net 1V2A: 948.82,365.16 1019.69,483.27
  text "8" at 5068.74,-349.25 h60 r90
  text "'.Pcb_File_Name_No_Path'    '.Layer_Name'    '.Print_Date'    '.Print_Time'" at 391.89,-1233.79 h60
plane 1 (plane layer: these items are gaps in the copper):
  rectangle: 472.44,-196.85 952.76,196.85
  rectangle: 4990.16,-718.5 5088.58,-295.28
  text "2" at 5068.74,-772.48 h60 r90
  text "'.Pcb_File_Name_No_Path'    '.Layer_Name'    '.Print_Date'    '.Print_Time'" at 391.89,-1233.79 h60
plane 2 (plane layer: these items are gaps in the copper):
  rectangle: 472.44,-196.85 952.76,196.85
  rectangle: 4990.16,-787.4 5088.58,-639.76
  rectangle: 4990.16,-570.87 5088.58,-295.28
  lines w10: 3736.53,-627.95 3086.61,-627.95 2968.5,-509.84 2620.08,-509.84 2582.68,-547.24 2582.68,-602.36 ; 3738.19,-627.95 3986.22,-875.98 4320.87,-875.98 4320.87,-600.39 4222.44,-501.97 4015.75,-501.97 3624.02,-110.24 3370.08,-110.24 3354.33,-125.98 3228.35,-125.98 3122.05,-19.68 3090.55,-19.68 3041.34,-68.9 2923.23,-68.9 2903.54,-88.58 2490.16,-88.58 2057.09,-88.58 2017.72,-127.95 1879.92,-127.95 1653.54,-354.33 679.13,-354.33 659.45,-374.02 659.45,-610.24 679.13,-629.92 2555.12,-629.92 ; 2555.12,-629.92 2582.68,-602.36 ; 2555.12,-629.92 2582.68,-602.36 ; 738.19,316.93 738.19,448.82 870.08,580.71 870.08,618.11 933.07,681.1 4435.04,681.1 4490.16,625.98 4490.16,364.17 4442.91,316.93 4035.43,316.93 3891.73,460.63 3230.31,460.63 3019.69,250 2523.62,250 2362.2,88.58 2185.04,88.58 2165.35,108.27 2135.83,108.27 1779.53,464.57 1232.28,464.57 1084.65,316.93 738.19,316.93
  text "4" at 5068.74,-624.84 h60 r90
  text "'.Pcb_File_Name_No_Path'    '.Layer_Name'    '.Print_Date'    '.Print_Time'" at 391.89,-1233.79 h60
plane 3 (plane layer: these items are gaps in the copper):
  rectangle: 4990.16,-787.4 5088.58,-570.87
  rectangle: 4990.16,-501.97 5088.58,-295.28
  lines w10: 0,-314.96 787.4,-314.96 787.4,-452.76 ; 0,188.98 118.11,188.98 118.11,814.96 259.84,814.96 492.13,1047.24 1354.33,1047.24 1354.33,807.09 ; 1122.05,1110.24 1122.05,1114.17 ; 1141.73,1110.24 1141.73,1114.17 ; 2787.4,1043.31 2787.4,555.12 2724.41,492.13 ; 2952.76,-1102.36 2952.76,-334.65 2381.89,-334.65 2381.89,-413.39 2444.88,-476.38 2708.66,-476.38 2708.66,-649.61 688.98,-649.61 688.98,-551.18 787.4,-452.76 ; 3744.09,-1114.17 3744.09,-696.85 4429.13,-696.85 4429.13,-452.76 4003.94,-452.76 4003.94,456.69 4377.95,456.69 ; 5031.5,275.59 5031.5,748.03 4685.04,748.03 4685.04,1043.31 3956.69,1043.31 3732.28,818.9 3051.18,818.9 3051.18,1043.31 2397.64,1043.31 2397.64,905.51 2299.21,807.09 1354.33,807.09 ; 5129.92,275.59 5129.92,279.53 5125.98,275.59 4377.95,275.59 4377.95,456.69 ; 787.4,-452.76 984.25,-452.76 984.25,236.22 1141.73,236.22 1141.73,472.44 728.35,472.44 728.35,669.29 1354.33,669.29 1354.33,807.09 ; 2724.41,492.13 2724.41,492.13 ; 2724.41,492.13 2610.24,492.13 2582.68,464.57 2582.68,342.52 2917.32,342.52 3208.66,633.86 4488.19,633.86 4488.19,515.75 4429.13,456.69 4377.95,456.69 ; 3145.67,-110.24 3370.08,-334.65 3759.84,-334.65 3759.84,393.7 3267.72,393.7 3145.67,271.65 3145.67,-110.24 ; 3248.03,161.42 3299.21,110.24 3527.56,110.24 3527.56,-173.23 3622.05,-173.23 3622.05,220.47 3248.03,220.47 3248.03,161.42
  text "5" at 5068.74,-555.94 h60 r90
  text "'.Pcb_File_Name_No_Path'    '.Layer_Name'     '.Print_Date'     '.Print_Time'" at 391.89,-1233.79 h60
plane 4 (plane layer: these items are gaps in the copper):
  rectangle: 4990.16,-364.17 5088.58,-295.28
  rectangle: 4990.16,-787.4 5088.58,-501.97
  text "7" at 5068.74,-418.15 h60 r90
  text "'.Pcb_File_Name_No_Path'    '.Layer_Name'    '.Print_Date'    '.Print_Time'" at 391.89,-1233.79 h60

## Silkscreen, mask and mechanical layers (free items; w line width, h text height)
Top Overlay:
  lines w4: 478.35,-187.01 944.88,-187.01 944.88,187.01 478.35,187.01 478.35,-187.01
  text "10_10_2020" at 350.08,-273.46 h60 r90
  text "ETL_RB_v1.5" at 218.95,-401.57 h80 r90
  text "'.Pcb_File_Name_No_Path'    '.Layer_Name'    '.Print_Date'    '.Print_Time'" at 387.95,-1233.79 h60
Bottom Overlay:
  text "ETL_RB_v1.5" at 199.27,397.64 h80 r90
  text "10_10_2020" at 326.46,273.46 h60 r90
  text "'.Pcb_File_Name_No_Path'    '.Layer_Name'    '.Print_Date'    '.Print_Time'" at 592.68,-1218.04 h60
Top Paste:
  text "'.Pcb_File_Name_No_Path'    '.Layer_Name'    '.Print_Date'    '.Print_Time'" at 384.02,-1237.72 h60
Bottom Paste:
  text "'.Pcb_File_Name_No_Path'    '.Layer_Name'    '.Print_Date'    '.Print_Time'" at 384.02,-1247.72 h60
Top Solder:
  text "'.Pcb_File_Name_No_Path'    '.Layer_Name'    '.Print_Date'    '.Print_Time'" at 384.02,-1237.72 h60
Bottom Solder:
  text "'.Pcb_File_Name_No_Path'    '.Layer_Name'    '.Print_Date'    '.Print_Time'" at 384.02,-1247.72 h60
Drill Guide:
  text "'.Pcb_File_Name_No_Path'    '.Layer_Name'    '.Print_Date'    '.Print_Time'" at 384.02,-1247.72 h60
Mechanical 1:
  the board outline again, w5.91
Mechanical 14:
  the board outline again, w5.91
  text "12X" at -682.91,-1100.24 h60
  text "'.Pcb_File_Name_No_Path'    '.Layer_Name'    '.Print_Date'    '.Print_Time'" at 391.89,-1231.97 h60
  text "We adopted the layer stack recommended by you. The stack file is included in the manufacturing documentation." at -631.73,-1344.02 h60
  text "The surfatce treatment of top and bottom layers is immersion gold." at -643.54,-1446.38 h60
  text "We have high voltage up to 1000V on some components, so please chose the solder mask material with this in mind." at -635.67,-1576.31 h60
  text "Traces with 0.12mm width are impedance controlled signals. Please tune the width to get to 50 Ohm." at -643.54,-1694.42 h60
Drill Drawing:
  text "'.Pcb_File_Name_No_Path'    '.Layer_Name'    '.Print_Date'    '.Print_Time'" at 391.89,-1233.79 h60

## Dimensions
5425.2,-1112.2 to 4933.07,1112.2 on Mechanical 14
5208.66,-1112.2 to 5129.92,915.35 on Mechanical 14
4933.07,-1112.2 to 5129.92,-915.35 on Mechanical 14
181.1,-944.88 to 51.18,-1062.99 on Mechanical 14
0,1736.22 to 5129.92,915.35 on Mechanical 14
0,1606.3 to 4933.07,1112.2 on Mechanical 14
0,1472.44 to 3620.08,1112.2 on Mechanical 14
0,1389.76 to 3226.38,1112.2 on Mechanical 14
0,1287.4 to 1903.54,1112.2 on Mechanical 14
0,1182.2 to 1509.84,1111.81 on Mechanical 14
0,915.35 to 196.85,1112.2 on Mechanical 14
